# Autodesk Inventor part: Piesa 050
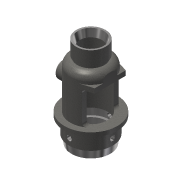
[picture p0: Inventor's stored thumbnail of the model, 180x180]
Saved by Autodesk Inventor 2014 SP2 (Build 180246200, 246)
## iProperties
Created: 2009-01
Part Number: Piesa 050
Document SubType Name: Modeling
Designer: Costel
Material: Steel, Cast
Density: 7.85 g/cm^3
Appearance: Steel - Cast
Mass: 1489.29 g
Surface Area: 670.465 cm^2
Volume: 189.718 cm^3
Author: Costel
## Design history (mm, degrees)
sketch "Sketch2"
  geometry: L1 (49.5, 0)-(-13.5, 0) reference; L2 (0, -15.4)-(0, 200.2) reference; L3 (22, 154)-(19, 142); L4 (19, 142)-(19, 119); L5 (19, 119)-(23, 119); L6 (28, 114)-(28, 32); L7 (28, 32)-(32, 32); L8 (32, 32)-(32, 18); L9 (32, 18)-(28, 18); L10 (28, 18)-(28, 0); L11 (28, 0)-(33, 0); L12 (33, 0)-(35, 14); L13 (35, 14)-(37, 14); L14 (37, 14)-(37, 36); L15 (37, 36)-(33, 36); L16 (33, 36)-(33, 40); L17 (33, 40)-(45, 40); L18 (45, 40)-(45, 47); L19 (45, 47)-(35, 47); L20 (35, 47)-(35, 114); L21 (23, 126)-(23, 126); L22 (23, 126)-(23, 130); L23 (23, 130)-(25, 130); L24 (25, 130)-(25, 154); L25 (25, 154)-(22, 154); L26 (32, 25)-(0, 25); A1 r 5 centre (23, 114) between (28, 114) and (23, 119); A2 r 12 centre (23, 114) between (35, 114) and (23, 126)
  constraints: 48 end point, 14 perpendicular, 8 parallel, 4 point on circle, 4 tangent, 2 centre point, 2 collinear, 1 midpoint, 1 point on line, 1 other
  dimensions: "d0" = 56 diameter of L10 L2; "d1" = 66 diameter of L11.end L2; "d2" = 154 distance between parallel lines of L11 L25; "d3" = 40 distance between parallel lines of L11 L17; "d4" = 7 distance of L17.end L18.end; "d5" = 14 vertical distance of L11.end L12.end; "d6" = 22 distance of L13.end L14.end; "d7" = 28 distance between parallel lines of L25 L21; "d8" = 35 distance between parallel lines of L25 L5; "d9" = 4 distance of L21.end L22.end; "d10" = 12 vertical distance of L3.start L3.end; "d11" = 90 diameter of L18 L2; "d12" = 70 diameter of L20 L2; "d14" = 64 diameter of L8 L2; "d15" = 50 diameter of L24 L2; "d16" = 38 diameter of L4 L2; "d17" = 44 diameter of L3.start L2; "d18" = 46 diameter of L22 L2; "d19" = 25 distance between parallel lines of L1 L26; "d20" = 14 distance between parallel lines of L9 L7; "d27" = 66 diameter of L16 L2; "d29" = 74 diameter of L14 L2; "d30" = 5 radius of A1; "d31" = 12 radius of A2; "d33" = 70 diameter of L12.end L2
revolve "Revolution1" sketch "Sketch2" stored, may be unused: angle "d32" = 90 deg
sketch "Sketch3"
  geometry: L1 (-45, 47)-(45, 47) reference; L2 (0, -15.4)-(0, 200.2) reference; L3 (-21, 47)-(-45, 47); L4 (-45, 47)-(-45, 102); L5 (-45, 102)-(-21, 102); L6 (-16, 97)-(-16, 52); L7 (-45, 47)-(-45, 40) reference; A1 r 5 centre (-21, 97) between (-16, 97) and (-21, 102); A2 r 5 centre (-21, 52) between (-21, 47) and (-16, 52); 1 further point
  constraints: 8 end point, 4 point on circle, 4 tangent, 2 centre point, 2 collinear, 2 parallel, 2 point on line, 1 equal radius, 1 horizontal, 1 perpendicular
  dimensions: "d34" = 55 distance of L3.end L4.end; "d35" = 5 radius of A1; "d37" = 16 distance between parallel lines of L2 L6
extrude "Extrusion1" cut sketch "Sketch3" stored distance "d38" = 10; taper "d39" = 0 deg
sketch "Sketch4"
  geometry: L1 (-14, -7)-(-12, -7); L2 (-12, -7)-(-12, 63); L3 (-12, 63)-(-14, 63); L4 (-14, 63)-(-14, -7); L5 (21, -26)-(21, 100) reference; A1 r 35 centre (21, 28) between (0, 56) and (0, 0) reference; A2 r 35 centre (21, 28) between (0, 56) and (0, 0) reference
  constraints: 8 end point, 3 tangent, 2 parallel, 1 horizontal, 1 perpendicular
  dimensions: "d40" = 33 distance between parallel lines of L5 L2
extrude "Extrusion2" cut sketch "Sketch4" stored distance "d42" = 10; taper "d43" = 0 deg
sketch "Sketch5"
  geometry: L1 (-12, 39.662)-(-12, 16.338) reference; L2 (0, 0)-(0, 9.48) reference; L3 (0, 46.52)-(0, 56) reference; L4 (75, 28)-(-51, 28) reference; L5 (-12, 1.5)-(-12, 54.5); L6 (-12, 1.5)-(10.753, -5.467); L7 (-12, 54.5)-(10.753, 61.467); A1 r 28 centre (21, 28) between (0, 46.52) and (0, 9.48) reference; A2 r 35 centre (21, 28) between (-12, 16.338) and (-12, 39.662) reference
  constraints: 6 end point, 2 point on circle, 2 tangent, 1 collinear, 1 perpendicular, 1 symmetric about line
  dimensions: "d45" = 53 distance of L5.start L5.end
extrude "Extrusion3" join sketch "Sketch5" distance "d46" = 8; taper "d47" = 0 deg
workplane "Work Plane1"
sketch "Sketch6"
  geometry: L1 (0, -15.4)-(0, 200.2) reference; L2 (-33, 0)-(33, 0) reference; C1 r 14 at (0, 86)
  constraints: 1 centre point, 1 point on line
  dimensions: "d49" = 28 diameter of C1; "d50" = 86 distance from line of L2 C1.centre
extrude "Extrusion4" join sketch "Sketch6" stored distance "d51" = 8; taper "d52" = 0 deg
chamfer "Chamfer1" distance "d53" = 2; stored, may be unused: second distance "d54" = 2, angle "d55" = 45 deg
hole "Hole1" diameter "d58" = 16; stored, may be unused: countersink angle "d62" = 90 deg, drill point angle "d64" = 118 deg; dims "d56" = 10, "d57" = 10, "d59" = 6, "d60" = 4, "d61" = 2, "d63" = 8
sketch "Sketch7"
  geometry: L1 (0, -15.4)-(0, 200.2) reference; L2 (-33, 0)-(33, 0) reference; 1 further point
  constraints: 1 point on line
  dimensions: "d65" = 25 distance from line of point (0, 25) L2 (= d19)
hole "Hole2" sketch "Sketch7" at (0, 25) diameter "d66" = 8; stored, may be unused: countersink angle "d70" = 90 deg, drill point angle "d72" = 118 deg; dims "d67" = 6, "d68" = 4, "d69" = 2, "d71" = 8
pattern_circular "Circular Pattern1" dims angle "d74" = 90 deg
fillet "Fillet1" dims "d76" = 3
body "Solid1"
other parameters: "d48" = -48
